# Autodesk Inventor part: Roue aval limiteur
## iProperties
Created: 2002-05
Part Number: Roue aval limiteur
Material: Par défaut
Document SubType Name: Modélisation
Designer: Flavien MARTY
Control State: 0
Master: False
Checked Out: False
Shininess: 20.0
Length Units: 11269
Angle Units: 11279
Time Units: 11290
Mass Units: 11283
Length Display Precision: 3
Angle Display Precision: 2
Compacted: True
Density: 0.0
Volumn: 0.0
Area: 0.0
PropertySet Name: Model Information
Author: Flavien MARTY
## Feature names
1. Extrusion1
2. Extrusion2
3. Congé1 [Fillet]
4. Perçage1 [Hole]
